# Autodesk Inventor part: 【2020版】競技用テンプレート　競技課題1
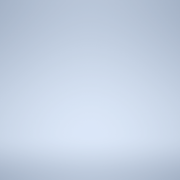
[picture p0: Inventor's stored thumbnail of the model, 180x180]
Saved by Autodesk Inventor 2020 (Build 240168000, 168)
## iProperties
Created: 2022-04
Part Number: 【2020版】競技用テンプレート　競技課題1
Material: 一般
Document SubType Name: Modeling
Designer: 競技委員会
Density: 1 g/cm^3
Appearance: 既定
Author: 競技委員会
Title: 事前展開用テンプレート
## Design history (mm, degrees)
